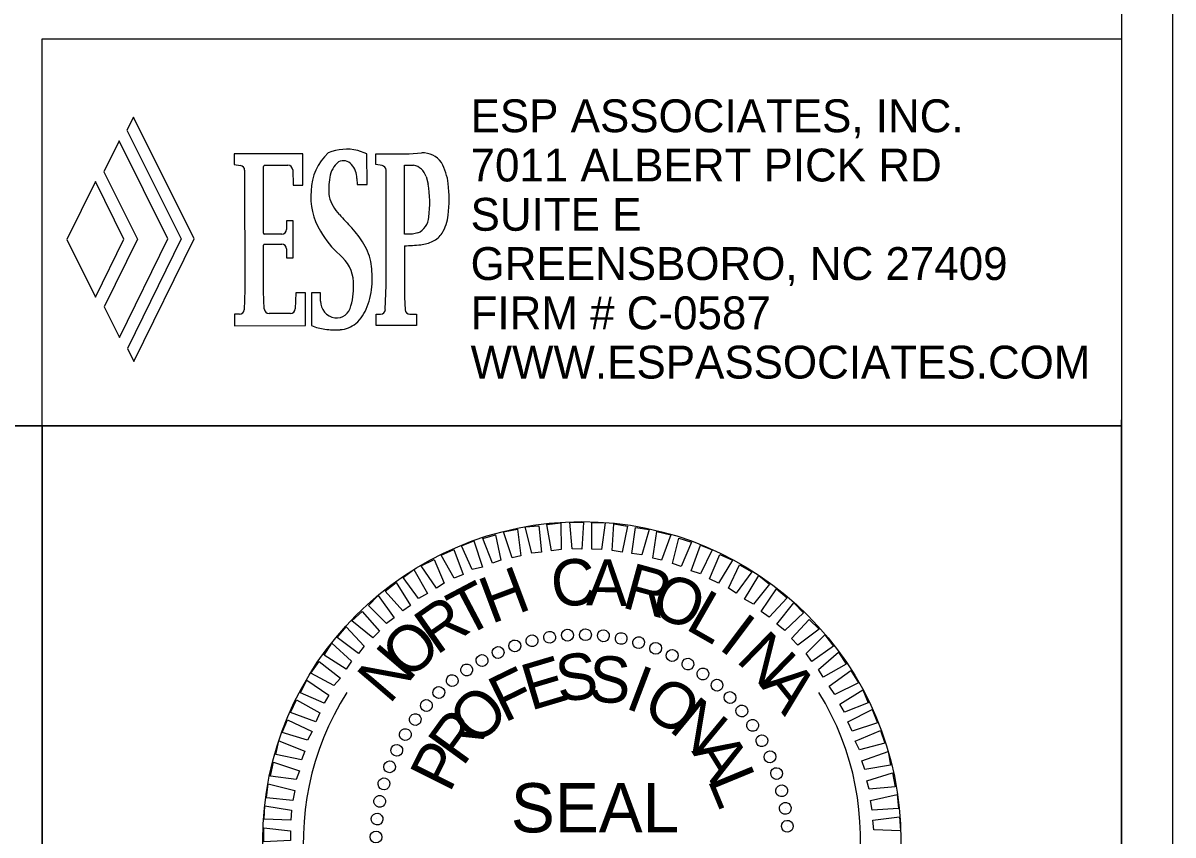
# Model space of a CAD drawing. Extents: x 265553 to 275568, y 168312 to 173522.
# Drawn here: x 273933.1 to 274213.2, y 172309.6 to 172507.4 of the extents above; entities that cross this region are included whole.
import ezdxf

# ---------------------------------------------------------------- set-up
doc = ezdxf.new("R2010")
doc.units = 0
for name, color, linetype in [('Default', 7, 'Continuous'), ('Geotech Sheets and Borders Cell', 7, 'Continuous'), ('Prop Strc Sect_ Border - minor', 7, 'Continuous'), ('Scratch_Level_0', 7, 'Continuous'), ('Scratch_Level_6', 7, 'Continuous'), ('Sheet Plot Border Inside CELL', 7, 'Continuous'), ('Sheet Professional Seal CELL', 7, 'Continuous')]:
    doc.layers.add(name, color=color, linetype=linetype)

msp = doc.modelspace()

# ---------------------------------------------------------------- linework, layer by layer
at = {"layer": 'Default'}
for p, q in [((274001.21, 172475.51), (273984.56, 172475.49)), ((273984.56, 172475.49), (273984.56, 172472.91)), ((274001.22, 172467.9), (274001.21, 172475.51)), ((274016.87, 172475.52), (274014.61, 172476.36)), ((274016.88, 172468.02), (274016.87, 172475.52)), ((274019.04, 172475.52), (274027.13, 172475.53)), ((274019.04, 172472.94), (274019.04, 172475.52)), ((274027.13, 172475.53), (274030.19, 172475.72)), ((273984.56, 172472.91), (273986.1, 172472.67)), ((273987.08, 172471.54), (273987.11, 172442.42)), ((273991.65, 172456.16), (273991.63, 172472.41)), ((273991.94, 172472.72), (273997.63, 172472.72)), ((273998.78, 172471.62), (273998.9, 172467.9)), ((274020.54, 172472.68), (274019.04, 172472.94)), ((274021.54, 172443.52), (274021.51, 172471.52)), ((274025.98, 172472.75), (274028.2, 172472.76)), ((274026, 172455.96), (274025.98, 172472.75)), ((274014.44, 172469.52), (274014.49, 172468.02)), ((274014.49, 172468.02), (274016.88, 172468.02)), ((274031.26, 172470), (274031.79, 172468.16)), ((273998.9, 172467.9), (274001.22, 172467.9)), ((273998.91, 172459.22), (273997.25, 172459.22)), ((273997.25, 172459.22), (273997.25, 172457.09)), ((273998.92, 172450.16), (273998.91, 172459.22)), ((273996.11, 172455.94), (273991.87, 172455.94)), ((274027.96, 172455.97), (274026, 172455.96)), ((274029.25, 172456.24), (274027.96, 172455.97)), ((273991.66, 172442.01), (273991.65, 172453.26)), ((273991.87, 172453.48), (273996.11, 172453.49)), ((273997.26, 172452.34), (273997.26, 172450.16)), ((274026, 172453.11), (274026.02, 172440.57)), ((273997.26, 172450.16), (273998.92, 172450.16)), ((274021.34, 172437.57), (274021.54, 172443.52)), ((273987.11, 172442.42), (273986.94, 172437.53)), ((273991.86, 172437.72), (273991.66, 172442.01)), ((273999.52, 172441.65), (273999.4, 172437.75)), ((274001.91, 172441.65), (273999.52, 172441.65)), ((274001.92, 172433.66), (274001.91, 172441.65)), ((274005.59, 172441.65), (274003.32, 172441.65)), ((274003.32, 172441.65), (274003.33, 172433.66)), ((274005.59, 172439.66), (274005.59, 172441.65)), ((274026.02, 172440.57), (274026.18, 172437.55)), ((273985.8, 172436.42), (273984.6, 172436.42)), ((273984.6, 172436.42), (273984.6, 172433.64)), ((273998.25, 172436.64), (273993.01, 172436.63)), ((274019.09, 172433.68), (274019.08, 172436.46)), ((274019.08, 172436.46), (274020.2, 172436.46)), ((274027.33, 172436.46), (274028.92, 172436.47)), ((274028.92, 172436.47), (274028.93, 172433.69)), ((273984.6, 172433.64), (274001.92, 172433.66)), ((274028.93, 172433.69), (274019.09, 172433.68))]:
    msp.add_line(p, q, dxfattribs=at)
for points in [[(273958.42, 172481.28), (273971.63, 172454.78), (273958.51, 172428.12), (273960.1, 172424.94), (273974.79, 172454.78), (273959.99, 172484.47), (273958.42, 172481.28)], [(273952.8, 172471.16), (273960.98, 172454.75), (273952.84, 172438.21), (273956.56, 172430.74), (273968.39, 172454.77), (273956.49, 172478.65), (273952.8, 172471.16)], [(273950.71, 172468.76), (273943.74, 172454.62), (273950.73, 172440.6), (273957.69, 172454.74), (273950.71, 172468.76)]]:
    msp.add_lwpolyline(points, dxfattribs=at)
for centre, radius, start, end in [((274012.03, 172464.74), 11.9, 77.4945, 112.607), ((274016.06, 172466.26), 12.79, 132.277, 178.7717), ((274011.15, 172471.24), 2.59, 40.3385, 117.3766), ((274030.52, 172470.3), 5.43, 34.4894, 93.4478), ((273985.93, 172471.54), 1.15, 0.0607, 81.368), ((273991.94, 172472.41), 0.31, 90.0607, 180.0607), ((273997.63, 172471.58), 1.15, 1.9943, 90.0607), ((274013.45, 172469.03), 5.7, 127.7022, 172.2101), ((274008.91, 172469.33), 5.53, 2.0028, 40.3385), ((274020.33, 172471.52), 1.18, 0.0607, 79.8192), ((274027.45, 172468.84), 3.99, 16.8704, 79.0876), ((274023.22, 172466.63), 13.56, 7.0821, 29.7759), ((274024.77, 172466.84), 17.22, 170.1104, 185.809), ((274003.88, 172463.66), 28.27, 352.8067, 9.1634), ((274001, 172464.63), 35.87, 353.4945, 5.8911), ((274019.19, 172464.98), 15.99, 174.413, 211.2268), ((274017.19, 172467.66), 9.9, 195.0144, 224.5602), ((274563.99, 172971.47), 753.4, 222.68215, 223.01817), ((274027.25, 172460.48), 4.69, 295.2092, 355.4805), ((274025.98, 172461.73), 10.73, 328.9362, 353.7339), ((273996.1, 172457.09), 1.15, 270.0607, 0.0607), ((273996.16, 172441.63), 23.23, 30.8042, 43.0163), ((273991.87, 172456.16), 0.22, 180.0607, 270.0607), ((274026.06, 172468.64), 23.76, 210.18, 228.2816), ((274029.13, 172462.14), 8.8, 275.4374, 295.5502), ((274030.58, 172459.09), 5.42, 295.5502, 327.7187), ((273991.87, 172453.26), 0.22, 90.0607, 180.0607), ((273996.11, 172452.34), 1.15, 0.0607, 90.0607), ((274004.59, 172446.53), 13.48, 9.1866, 31.2488), ((274023.06, 172525.9), 72.85, 272.3182, 275.4374), ((274004.5, 172443.85), 9.09, 3.0107, 50.83), ((273994.56, 172445.27), 23.59, 356.494, 8.3188), ((273997.95, 172443.03), 15.68, 343.132, 4.7325), ((274001.38, 172444.49), 16.73, 338.2327, 357.7166), ((273985.8, 172437.57), 1.15, 270.0607, 358.0948), ((273993.01, 172437.78), 1.15, 183.0592, 270.0607), ((273998.25, 172437.79), 1.15, 270.0607, 358.1271), ((274009.69, 172439.6), 4.1, 179.1725, 260.7014), ((274009.48, 172439.05), 3.52, 262.5493, 350.6871), ((274007.06, 172441.91), 10.51, 312.5245, 339.8341), ((274020.2, 172437.6), 1.15, 270.0607, 358.0948), ((274027.32, 172437.61), 1.15, 183.0592, 270.0607), ((274008.48, 172446.82), 14.13, 248.6025, 262.4993), ((274009.16, 172452.25), 19.61, 262.6129, 273.4517), ((274009.78, 172439.78), 7.12, 274.5621, 307.9936)]:
    msp.add_arc(centre, radius, start, end, dxfattribs=at)
at = {"layer": 'Geotech Sheets and Borders Cell'}
for points in [[(272700.69, 173192.58), (274200.69, 173192.58), (274200.69, 172142.58), (272700.69, 172142.58)], [(273674.76, 172409.27), (273937.73, 172409.27), (273937.73, 172161.9), (273674.76, 172161.9)], [(273937.73, 172409.27), (274200.69, 172409.27), (274200.69, 172161.9), (273937.73, 172161.9)]]:
    msp.add_lwpolyline(points, close=True, dxfattribs=at)
msp.add_lwpolyline([(274200.69, 172409.27), (273674.76, 172409.27), (273674.76, 172142.58), (274200.69, 172142.58), (274200.69, 172410.73)], dxfattribs=at)
at = {"layer": 'Scratch_Level_0'}
msp.add_ellipse((274069.21, 172308.22), major_axis=(45.09, 51.04), ratio=0.993455, start_param=1.731198, end_param=5.992706, dxfattribs=at)
at = {"layer": 'Scratch_Level_6'}
msp.add_lwpolyline([(273937.73, 172503.53), (274200.69, 172503.53), (274200.69, 172409.27), (273937.73, 172409.27)], close=True, dxfattribs=at)
msp.add_circle((274069.21, 172308.22), 77.7, dxfattribs=at)
at = {"layer": 'Sheet Plot Border Inside CELL'}
msp.add_lwpolyline([(272545.53, 172139.74), (274213.19, 172139.74), (274213.19, 173195.41), (272545.53, 173195.41)], close=True, dxfattribs=at)
at = {"layer": 'Sheet Professional Seal CELL'}
for p, q in [((274057.01, 172356.92), (274057.01, 172356.92)), ((274061.41, 172357.72), (274061.41, 172357.72)), ((274065.71, 172358.32), (274065.71, 172358.32)), ((274070.11, 172358.42), (274070.11, 172358.42)), ((274074.51, 172358.12), (274074.51, 172358.12)), ((274078.81, 172357.42), (274078.81, 172357.42)), ((274083.01, 172356.52), (274083.01, 172356.52)), ((274048.81, 172354.12), (274048.81, 172354.12)), ((274052.81, 172355.72), (274052.81, 172355.72)), ((274087.21, 172355.12), (274087.21, 172355.12)), ((274091.21, 172353.32), (274091.21, 172353.32)), ((274044.91, 172352.12), (274044.91, 172352.12)), ((274095.11, 172351.32), (274095.11, 172351.32)), ((274041.11, 172349.82), (274041.11, 172349.82)), ((274098.71, 172348.82), (274098.71, 172348.82)), ((274037.61, 172347.32), (274037.61, 172347.32)), ((274102.21, 172346.12), (274102.21, 172346.12)), ((274034.31, 172344.32), (274034.31, 172344.32)), ((274105.31, 172343.12), (274105.31, 172343.12)), ((274031.31, 172341.22), (274031.31, 172341.22)), ((274108.31, 172339.82), (274108.31, 172339.82)), ((274028.61, 172337.72), (274028.61, 172337.72)), ((274026.11, 172334.12), (274026.11, 172334.12)), ((274110.81, 172336.32), (274110.81, 172336.32)), ((274113.11, 172332.52), (274113.11, 172332.52)), ((274024.11, 172330.22), (274024.11, 172330.22)), ((274115.11, 172328.62), (274115.11, 172328.62)), ((274022.31, 172326.22), (274022.31, 172326.22)), ((274116.71, 172324.62), (274116.71, 172324.62)), ((274020.91, 172322.02), (274020.91, 172322.02)), ((274117.91, 172320.42), (274117.91, 172320.42)), ((274020.01, 172317.82), (274020.01, 172317.82)), ((274118.71, 172316.02), (274118.71, 172316.02)), ((274019.31, 172313.52), (274019.31, 172313.52)), ((274119.31, 172311.72), (274119.31, 172311.72))]:
    msp.add_line(p, q, dxfattribs=at)
for points in [[(274052.21, 172377.12), (274050.11, 172383.42), (274053.51, 172384.12), (274054.31, 172377.62)], [(274057.01, 172378.22), (274055.41, 172384.62), (274058.71, 172384.92), (274059.41, 172378.52)], [(274061.81, 172378.82), (274060.71, 172385.22), (274064.11, 172385.62), (274064.21, 172379.12)], [(274066.81, 172379.32), (274066.31, 172385.82), (274069.61, 172385.72), (274069.21, 172379.22)], [(274071.61, 172379.22), (274071.61, 172385.72), (274074.91, 172385.62), (274074.01, 172379.12)], [(274076.61, 172378.92), (274077.01, 172385.42), (274080.31, 172384.82), (274079.01, 172378.52)], [(274081.41, 172378.12), (274082.31, 172384.52), (274085.61, 172384.02), (274083.81, 172377.82)], [(274042.51, 172374.22), (274039.91, 172380.02), (274042.91, 172381.22), (274045.01, 172374.82)], [(274047.41, 172375.82), (274045.11, 172381.82), (274048.21, 172382.72), (274049.51, 172376.52)], [(274086.51, 172377.02), (274087.51, 172383.52), (274090.91, 172382.72), (274088.61, 172376.52)], [(274091.31, 172375.72), (274092.81, 172381.92), (274095.91, 172380.92), (274093.41, 172375.02)], [(274038.11, 172372.12), (274034.91, 172377.72), (274038.01, 172379.12), (274040.31, 172373.02)], [(274095.81, 172373.92), (274098.11, 172380.22), (274100.91, 172379.02), (274098.11, 172373.22)], [(274033.81, 172369.72), (274030.11, 172375.12), (274033.21, 172376.72), (274035.71, 172370.92)], [(274100.31, 172372.02), (274102.81, 172377.92), (274105.91, 172376.52), (274102.51, 172370.92)], [(274029.41, 172367.22), (274025.71, 172372.32), (274028.31, 172374.22), (274031.61, 172368.42)], [(274104.91, 172369.72), (274107.61, 172375.42), (274110.61, 172373.72), (274106.81, 172368.52)], [(274108.81, 172367.02), (274112.31, 172372.82), (274114.91, 172370.72), (274111.01, 172365.82)], [(274025.61, 172364.22), (274021.31, 172369.02), (274024.01, 172371.12), (274027.51, 172365.52)], [(274021.61, 172361.12), (274017.21, 172365.52), (274019.61, 172367.92), (274023.51, 172362.52)], [(274112.91, 172364.02), (274116.61, 172369.52), (274119.21, 172367.32), (274114.81, 172362.62)], [(274116.71, 172360.92), (274120.81, 172366.12), (274123.21, 172363.72), (274118.61, 172359.42)], [(274018.31, 172357.62), (274013.21, 172361.72), (274015.71, 172364.02), (274019.91, 172359.22)], [(274120.31, 172357.42), (274124.61, 172362.12), (274127.01, 172359.72), (274121.81, 172355.82)], [(274014.81, 172353.82), (274009.61, 172357.72), (274011.81, 172360.32), (274016.21, 172355.62)], [(274011.81, 172350.02), (274006.41, 172353.42), (274008.31, 172356.32), (274013.11, 172351.92)], [(274123.81, 172353.82), (274128.41, 172358.32), (274130.51, 172355.62), (274125.21, 172351.82)], [(274126.81, 172349.92), (274131.71, 172354.12), (274133.61, 172351.22), (274128.01, 172348.02)], [(274008.81, 172346.02), (274003.21, 172349.02), (274005.21, 172351.82), (274010.41, 172347.82)], [(274129.41, 172345.82), (274134.71, 172349.62), (274136.61, 172346.62), (274130.81, 172343.82)], [(274006.41, 172341.72), (274000.71, 172344.22), (274002.21, 172347.32), (274007.61, 172343.62)], [(274132.01, 172341.42), (274137.61, 172344.92), (274138.91, 172341.82), (274133.21, 172339.52)], [(274004.41, 172337.12), (273998.21, 172339.42), (273999.71, 172342.52), (274005.41, 172339.32)], [(274134.01, 172337.12), (274139.91, 172340.12), (274141.21, 172336.92), (274135.01, 172334.92)], [(274002.41, 172332.72), (273996.21, 172334.52), (273997.51, 172337.62), (274003.51, 172334.82)], [(274135.81, 172332.42), (274141.91, 172335.02), (274143.01, 172331.92), (274136.81, 172330.32)], [(274000.91, 172327.92), (273994.71, 172329.22), (273995.41, 172332.52), (274001.71, 172330.02)], [(274137.41, 172327.62), (274143.81, 172329.92), (274144.41, 172326.62), (274138.11, 172325.52)], [(273999.61, 172323.12), (273993.41, 172323.92), (273994.11, 172327.32), (274000.41, 172325.22)], [(274138.61, 172322.82), (274144.91, 172324.72), (274145.51, 172321.32), (274139.21, 172320.72)], [(273998.81, 172318.02), (273992.41, 172318.62), (273992.81, 172322.02), (273999.31, 172320.42)], [(274139.51, 172318.02), (274146.01, 172319.42), (274146.31, 172316.02), (274139.91, 172315.62)], [(273998.31, 172313.22), (273991.81, 172313.42), (273992.01, 172316.72), (273998.51, 172315.62)], [(274140.11, 172313.22), (274146.61, 172314.02), (274146.81, 172310.62), (274140.31, 172310.82)], [(273998.21, 172308.22), (273991.71, 172307.92), (273991.71, 172311.32), (273998.21, 172310.62)]]:
    msp.add_lwpolyline(points, close=True, dxfattribs=at)
for centre, major_axis in [((274061.36, 172357.76), (-0.23, 1.42)), ((274065.71, 172358.26), (-0.1, 1.44)), ((274070.09, 172358.37), (0.03, 1.44)), ((274074.45, 172358.11), (0.15, 1.43)), ((274078.78, 172357.46), (0.27, 1.41)), ((274052.88, 172355.65), (-0.47, 1.36)), ((274057.08, 172356.89), (-0.35, 1.4)), ((274083.04, 172356.44), (0.4, 1.38)), ((274087.19, 172355.05), (0.52, 1.34)), ((274044.89, 172352.09), (-0.7, 1.26)), ((274048.81, 172354.05), (-0.59, 1.32)), ((274091.2, 172353.31), (0.63, 1.29)), ((274041.16, 172349.81), (-0.81, 1.19)), ((274095.04, 172351.22), (0.74, 1.23)), ((274098.69, 172348.8), (0.85, 1.16)), ((274037.64, 172347.2), (-0.91, 1.12)), ((274102.12, 172346.08), (0.94, 1.09)), ((274034.37, 172344.3), (-1, 1.04)), ((274031.35, 172341.13), (-1.09, 0.94)), ((274105.29, 172343.07), (1.04, 1)), ((274028.63, 172337.71), (-1.16, 0.85)), ((274108.19, 172339.79), (1.12, 0.91)), ((274110.8, 172336.27), (1.19, 0.81)), ((274026.21, 172334.06), (-1.23, 0.74)), ((274113.08, 172332.54), (1.26, 0.7)), ((274024.13, 172330.21), (-1.29, 0.63)), ((274115.03, 172328.62), (1.32, 0.59)), ((274022.38, 172326.2), (-1.34, 0.52)), ((274116.64, 172324.55), (1.36, 0.47)), ((274020.99, 172322.05), (-1.38, 0.4)), ((274117.88, 172320.36), (1.4, 0.35)), ((274019.97, 172317.79), (-1.41, 0.27)), ((274118.75, 172316.07), (1.42, 0.23)), ((274019.33, 172313.46), (-1.43, 0.15)), ((274119.25, 172311.72), (1.44, 0.1)), ((274019.06, 172309.1), (-1.44, 0.03))]:
    msp.add_ellipse(centre, major_axis=major_axis, ratio=0.999708, dxfattribs=at)

# ---------------------------------------------------------------- texts
at = {"layer": 'Prop Strc Sect_ Border - minor'}
for s, p in [('ESP ASSOCIATES, INC.', (274042.11, 172480.78)), ('7011 ALBERT PICK RD', (274042.11, 172468.78)), ('SUITE E', (274042.11, 172456.78)), ('GREENSBORO, NC 27409 ', (274042.11, 172444.78)), ('FIRM # C-0587', (274042.11, 172432.78)), ('WWW.ESPASSOCIATES.COM', (274042.11, 172420.78))]:
    msp.add_text(s, height=8, dxfattribs=at).set_placement(p)
at = {"layer": 'Sheet Professional Seal CELL'}
for s, rotation, p in [('C', 6.2199, (274062.31, 172364.92)), ('A', 359.0203, (274070.21, 172365.52)), ('R', 344.6211, (274078.61, 172365.12)), ('H', 20.6195, (274047.11, 172360.92)), ('O', 337.4212, (274085.31, 172363.62)), ('T', 27.8198, (274040.61, 172357.62)), ('L', 330.2209, (274094.11, 172359.92)), ('R', 35.0205, (274033.81, 172353.22)), ('I', 323.0201, (274102.21, 172355.12)), ('O', 42.2217, (274026.91, 172347.02)), ('N', 315.8189, (274106.51, 172352.02)), ('N', 49.4235, (274022.31, 172341.22)), ('E', 16.6111, (274056.71, 172339.82)), ('S', 7.2556, (274063.61, 172341.92)), ('S', 357.9004, (274070.81, 172342.02)), ('F', 25.967, (274050.31, 172336.82)), ('I', 339.1896, (274079.41, 172340.62)), ('A', 308.6172, (274112.41, 172346.12)), ('O', 44.6812, (274043.71, 172330.92)), ('O', 329.8335, (274083.41, 172339.22)), ('N', 320.4766, (274090.11, 172335.22)), ('R', 54.0397, (274040.21, 172326.02)), ('P', 63.3989, (274037.01, 172319.62)), ('A', 301.7603, (274095.81, 172330.02)), ('L', 292.4008, (274099.71, 172323.12))]:
    msp.add_text(s, height=11.28, rotation=rotation, dxfattribs=at).set_placement(p)
msp.add_text('SEAL', height=11.996, dxfattribs=at).set_placement((274051.92, 172310.22))

doc.saveas('drawing.dxf')
